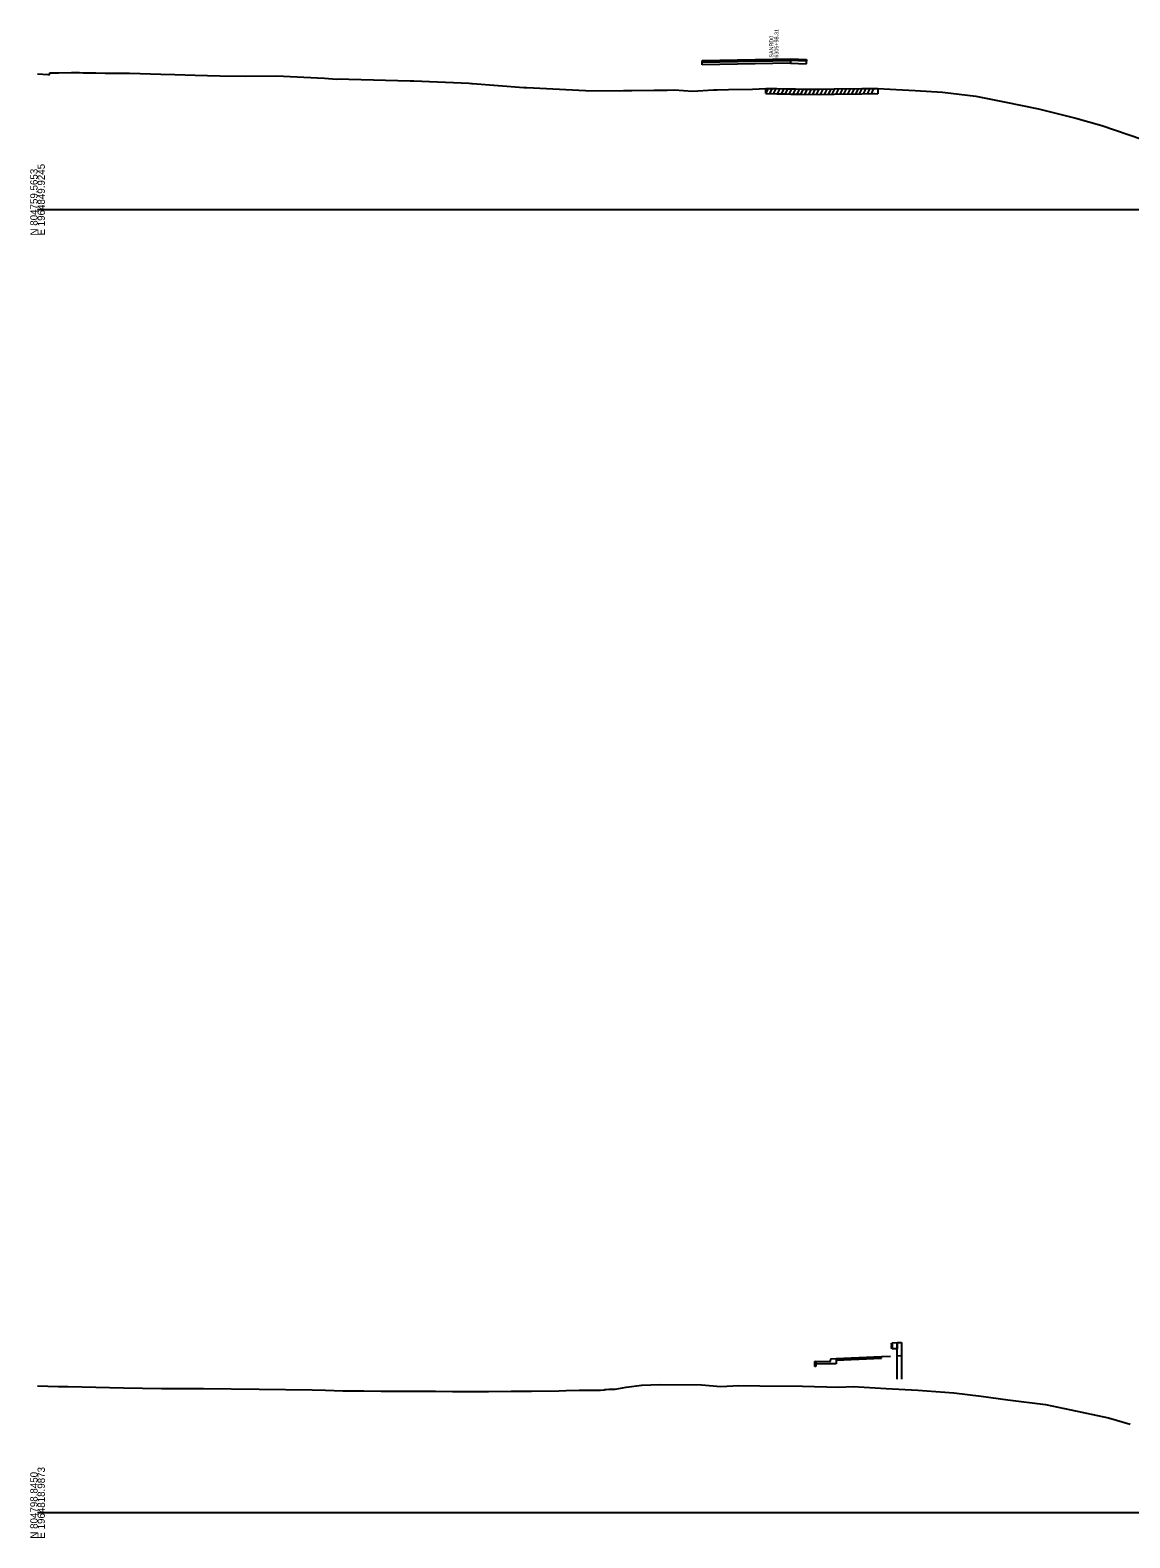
# Model space of a CAD drawing. Extents: x 1017 to 19997, y -1947 to 50737.
# Drawn here: x 11997 to 12419, y 5990 to 6569 of the extents above; entities that cross this region are included whole.
import ezdxf

# ---------------------------------------------------------------- set-up
doc = ezdxf.new("R2010")
doc.units = 0
for name, color, linetype in [('Default', 7, 'Continuous'), ('RD_GPK_XS_Cell', 7, 'Continuous'), ('RD_XS_Base', 7, 'Continuous'), ('RD_XS_CurbBase', 7, 'Continuous'), ('RD_XS_ExGround', 7, 'Continuous'), ('RD_XS_ExPaveRet', 7, 'Continuous'), ('RD_XS_GR', 7, 'Continuous'), ('RD_XS_Greenside', 7, 'Continuous'), ('RD_XS_Pave', 7, 'Continuous'), ('RD_XS_PaveOvlay', 7, 'Continuous'), ('RD_XS_SW', 7, 'Continuous'), ('RD_XS_SWbase', 7, 'Continuous'), ('RD_XS_TX_Notes', 7, 'Continuous')]:
    doc.layers.add(name, color=color, linetype=linetype)

msp = doc.modelspace()

# ---------------------------------------------------------------- linework, layer by layer
at = {"layer": 'RD_GPK_XS_Cell'}
for p, q in [((12000, 6500), (12600, 6500)), ((12000, 6000), (12600, 6000))]:
    msp.add_line(p, q, dxfattribs=at)
at = {"layer": 'RD_XS_Base'}
for points in [[(12254.92, 6556.5), (12282.01, 6557.03), (12288.89, 6557.12)], [(12254.92, 6555.5), (12254.92, 6556.5)], [(12288.89, 6556.12), (12282.01, 6556.03), (12254.92, 6555.5)], [(12288.89, 6557.12), (12288.89, 6556.12)], [(12294.95, 6556.84), (12288.89, 6557.12)], [(12288.89, 6556.12), (12294.95, 6555.84)], [(12294.95, 6555.84), (12294.95, 6556.84)], [(12298.19, 6057.38), (12298.58, 6057.4)], [(12298.19, 6056.05), (12298.19, 6057.38)], [(12298.58, 6057.4), (12298.58, 6056.07)], [(12298.58, 6056.07), (12298.19, 6056.05)]]:
    msp.add_lwpolyline(points, dxfattribs=at)
at = {"layer": 'RD_XS_CurbBase'}
for points in [[(12298.58, 6057.99), (12304.06, 6058.02), (12304.38, 6059.03), (12306.31, 6059.1)], [(12298.58, 6056.99), (12298.58, 6057.99)], [(12306.31, 6057.1), (12304.06, 6057.02), (12298.58, 6056.99)], [(12306.31, 6059.1), (12306.31, 6057.1)]]:
    msp.add_lwpolyline(points, dxfattribs=at)
at = {"layer": 'RD_XS_ExGround'}
for points in [[(12000, 6551.99), (12004, 6551.8), (12004.53, 6551.81), (12004.69, 6552.39), (12006.69, 6552.39), (12008.11, 6552.37), (12012.96, 6552.58), (12016.1, 6552.49), (12017.52, 6552.45), (12022.4, 6552.46), (12025.92, 6552.25), (12035.33, 6552.26), (12039.35, 6552.17), (12047.28, 6551.91), (12052.69, 6551.74), (12060.46, 6551.49), (12069.97, 6551.25), (12079.79, 6551.18), (12091.69, 6551.29), (12110.05, 6550.31), (12114.63, 6549.98), (12115.93, 6550.08), (12119.46, 6550.01), (12142.95, 6549.31), (12144.36, 6549.31), (12165.51, 6548.43), (12166.41, 6548.3), (12166.91, 6548.31), (12186.53, 6546.84), (12187.69, 6546.75), (12210.19, 6545.58), (12211.4, 6545.57), (12224.79, 6545.59), (12227.95, 6545.58), (12236.55, 6545.79), (12241.55, 6545.81), (12244.33, 6545.85), (12251.26, 6545.44), (12259.25, 6545.89), (12260.66, 6545.92), (12265.08, 6546.03), (12274.27, 6546.12), (12279.36, 6546.44), (12283.6, 6546.37), (12287.09, 6546.32), (12288.96, 6546.28), (12290.71, 6546.25), (12293.35, 6546.2), (12300.05, 6546.1), (12305.58, 6546.23), (12316.22, 6546.35), (12320.77, 6546.43), (12321.08, 6546.44), (12322.34, 6546.41), (12331.85, 6545.94), (12336.61, 6545.69), (12347.09, 6544.94), (12359.99, 6543.49), (12370.78, 6541.28), (12383.95, 6538.64), (12398.27, 6535.02), (12408.26, 6532.18), (12423.66, 6527.03)], [(12000, 6048.6), (12007.89, 6048.33), (12010.3, 6048.35), (12010.92, 6048.35), (12011.72, 6048.35), (12033.02, 6047.92), (12047.51, 6047.67), (12063.63, 6047.61), (12084.97, 6047.37), (12105.32, 6047.06), (12110.5, 6046.95), (12117.08, 6046.77), (12125.2, 6046.71), (12131.85, 6046.62), (12141.33, 6046.57), (12143.97, 6046.55), (12152.71, 6046.53), (12159.21, 6046.48), (12161.59, 6046.46), (12172.99, 6046.48), (12181.63, 6046.57), (12189.46, 6046.61), (12200.01, 6046.76), (12202.75, 6046.79), (12207.8, 6046.97), (12209.39, 6046.99), (12210.21, 6047), (12215.92, 6046.98), (12217.3, 6047.12), (12217.62, 6047.18), (12218.08, 6047.23), (12219.13, 6047.32), (12220.19, 6047.33), (12221.6, 6047.34), (12225.86, 6048.07), (12231.79, 6048.9), (12235.29, 6049.07), (12238.44, 6049.19), (12254.66, 6049.04), (12262.17, 6048.39), (12269.08, 6048.78), (12277.13, 6048.61), (12293.46, 6048.52), (12307.42, 6048.07), (12312.85, 6048.36), (12325.49, 6047.62), (12337.65, 6046.99), (12351.54, 6045.95), (12362.03, 6044.72), (12372.17, 6043.28), (12386.7, 6041.53), (12396.36, 6039.41), (12410.78, 6036.4), (12419.18, 6033.96)]]:
    msp.add_lwpolyline(points, dxfattribs=at)
at = {"layer": 'RD_XS_ExPaveRet'}
for p, q in [((12279.36, 6544.44), (12279.36, 6546.44)), ((12279.36, 6544.44), (12280.36, 6546.42)), ((12279.36, 6544.44), (12283.6, 6544.37)), ((12280.86, 6544.42), (12281.86, 6546.4)), ((12282.36, 6544.39), (12283.36, 6546.37)), ((12283.6, 6544.37), (12287.09, 6544.32)), ((12283.86, 6544.36), (12284.86, 6546.35)), ((12285.36, 6544.34), (12286.36, 6546.33)), ((12286.86, 6544.32), (12287.86, 6546.3)), ((12287.09, 6544.32), (12288.96, 6544.28)), ((12288.36, 6544.29), (12289.35, 6546.27)), ((12288.96, 6544.28), (12290.71, 6544.25)), ((12289.86, 6544.26), (12290.85, 6546.24)), ((12290.71, 6544.25), (12293.35, 6544.2)), ((12291.36, 6544.23), (12292.36, 6546.22)), ((12292.86, 6544.21), (12293.86, 6546.19)), ((12293.35, 6544.2), (12300.05, 6544.1)), ((12294.36, 6544.18), (12295.36, 6546.17)), ((12295.86, 6544.16), (12296.86, 6546.15)), ((12297.36, 6544.14), (12298.36, 6546.12)), ((12298.86, 6544.12), (12299.86, 6546.1)), ((12300.05, 6544.1), (12305.58, 6544.23)), ((12300.36, 6544.1), (12301.38, 6546.13)), ((12301.86, 6544.14), (12302.88, 6546.16)), ((12303.36, 6544.17), (12304.38, 6546.2)), ((12304.86, 6544.21), (12305.87, 6546.23)), ((12305.58, 6544.23), (12316.22, 6544.35)), ((12306.36, 6544.23), (12307.37, 6546.25)), ((12307.86, 6544.25), (12308.87, 6546.26)), ((12309.36, 6544.27), (12310.37, 6546.28)), ((12310.86, 6544.29), (12311.87, 6546.3)), ((12312.36, 6544.31), (12313.37, 6546.32)), ((12313.86, 6544.32), (12314.87, 6546.34)), ((12315.36, 6544.34), (12316.37, 6546.35)), ((12316.22, 6544.35), (12320.77, 6544.43)), ((12316.86, 6544.36), (12317.87, 6546.38)), ((12318.36, 6544.39), (12319.37, 6546.41)), ((12319.86, 6544.42), (12320.87, 6546.43)), ((12320.77, 6544.43), (12321.08, 6544.44)), ((12321.08, 6544.44), (12322.34, 6544.41)), ((12322.34, 6546.41), (12322.34, 6544.41))]:
    msp.add_line(p, q, dxfattribs=at)
at = {"layer": 'RD_XS_GR'}
for points in [[(12328.01, 6065.15), (12327.19, 6064.52)], [(12327.19, 6064.52), (12327.98, 6063.95)], [(12327.98, 6063.95), (12327.19, 6063.36)], [(12327.19, 6063.36), (12328.01, 6062.79)], [(12328.01, 6065.15), (12329.7, 6065.21)], [(12328.01, 6062.79), (12328.01, 6065.15)], [(12329.7, 6062.85), (12328.01, 6062.79)], [(12329.7, 6065.21), (12331.38, 6065.27)], [(12329.7, 6060.19), (12329.7, 6065.21)], [(12329.7, 6065.21), (12329.7, 6062.85)], [(12331.38, 6065.27), (12331.38, 6060.27)], [(12329.7, 6060.19), (12331.38, 6060.27)], [(12329.7, 6051.19), (12329.7, 6060.19)], [(12331.38, 6060.27), (12331.38, 6051.25)]]:
    msp.add_lwpolyline(points, dxfattribs=at)
at = {"layer": 'RD_XS_Greenside'}
msp.add_lwpolyline([(12323.77, 6059.91), (12327.19, 6060.07)], dxfattribs=at)
at = {"layer": 'RD_XS_Pave'}
for points in [[(12288.89, 6557.44), (12282.01, 6557.35), (12254.92, 6556.81)], [(12254.92, 6556.5), (12282.01, 6557.03), (12288.89, 6557.12)], [(12254.92, 6556.81), (12254.92, 6556.5)], [(12288.89, 6557.12), (12288.89, 6557.44)], [(12288.89, 6557.44), (12294.95, 6557.17)], [(12294.95, 6556.84), (12288.89, 6557.12)], [(12294.95, 6557.17), (12294.95, 6556.84)], [(12298.19, 6057.7), (12298.58, 6057.72)], [(12298.19, 6057.38), (12298.19, 6057.7)], [(12298.58, 6057.4), (12298.19, 6057.38)], [(12298.58, 6057.72), (12298.58, 6057.4)]]:
    msp.add_lwpolyline(points, dxfattribs=at)
at = {"layer": 'RD_XS_PaveOvlay'}
for points in [[(12254.92, 6557.13), (12282.01, 6557.66), (12288.89, 6557.75)], [(12288.89, 6557.44), (12282.01, 6557.35), (12254.92, 6556.81)], [(12254.92, 6556.81), (12254.92, 6557.13)], [(12288.89, 6557.75), (12288.89, 6557.44)], [(12288.89, 6557.75), (12294.95, 6557.49)], [(12294.95, 6557.17), (12288.89, 6557.44)], [(12294.95, 6557.49), (12294.95, 6557.17)], [(12298.19, 6058.02), (12298.58, 6058.04)], [(12298.19, 6057.7), (12298.19, 6058.02)], [(12298.58, 6057.72), (12298.19, 6057.7)], [(12298.58, 6058.04), (12298.58, 6057.99), (12298.58, 6057.72)]]:
    msp.add_lwpolyline(points, dxfattribs=at)
at = {"layer": 'RD_XS_SW'}
msp.add_lwpolyline([(12306.31, 6059.1), (12323.77, 6059.91)], dxfattribs=at)
at = {"layer": 'RD_XS_SWbase'}
for points in [[(12306.31, 6058.44), (12323.77, 6059.25)], [(12306.31, 6059.1), (12306.31, 6058.44)], [(12323.77, 6059.25), (12323.77, 6059.91)]]:
    msp.add_lwpolyline(points, dxfattribs=at)

# ---------------------------------------------------------------- texts
at = {"layer": 'Default'}
for p in [(12000, 6500), (12000, 6000)]:
    msp.add_text('-', height=0.0001, dxfattribs=at).set_placement(p)
at = {"layer": 'RD_GPK_XS_Cell'}
for s, p in [('N 804759.5653', (12000, 6490)), ('E 1964849.9245', (12002.8, 6490)), ('E 1964818.9873', (12002.8, 5990)), ('N 804798.8450', (12000, 5990))]:
    msp.add_text(s, height=2.8, rotation=90, dxfattribs=at).set_placement(p)
at = {"layer": 'RD_XS_TX_Notes'}
for s, p in [(' SANRD0', (12282.26, 6557.68)), (' 6305+98.31', (12284.21, 6557.68))]:
    msp.add_text(s, height=1.5, rotation=90, dxfattribs=at).set_placement(p)

doc.saveas('drawing.dxf')
